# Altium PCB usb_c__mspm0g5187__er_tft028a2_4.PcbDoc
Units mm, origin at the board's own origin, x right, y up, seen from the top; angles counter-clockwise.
Board outline 64 x 33 mm, 2 copper layers (Top, Bottom), stack 0 mm thick; 33 components, 30 nets, 216 pads, 98 vias.
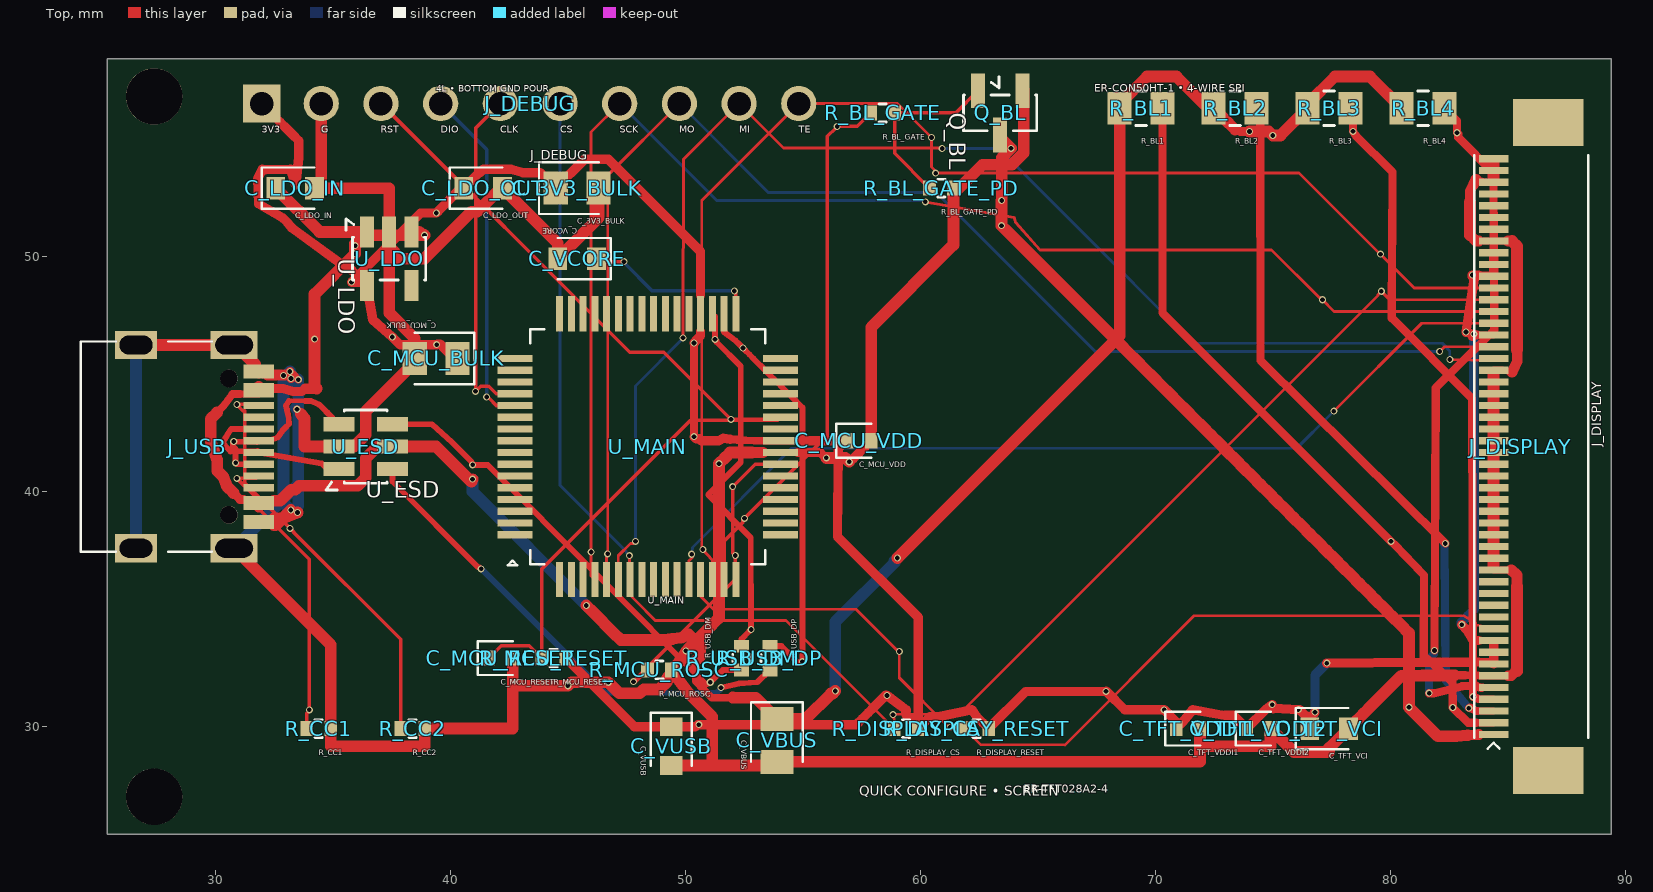
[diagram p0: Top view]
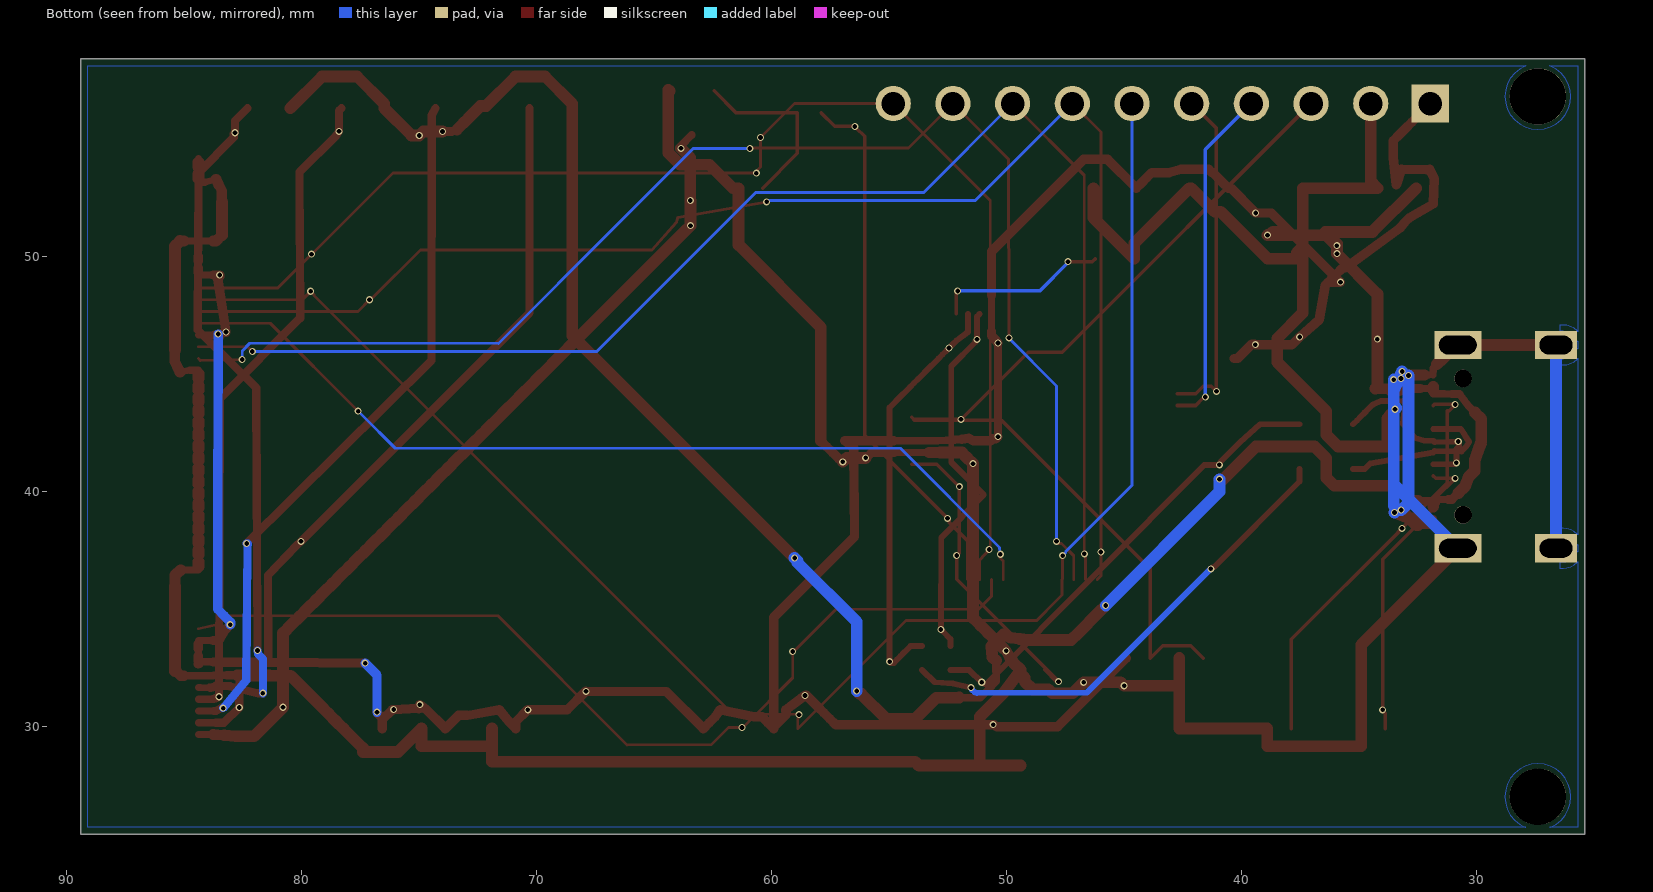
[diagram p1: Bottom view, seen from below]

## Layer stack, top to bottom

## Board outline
25.4,58.4 89.4,58.4 89.4,25.4 25.4,25.4

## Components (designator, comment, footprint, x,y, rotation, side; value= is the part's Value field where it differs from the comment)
C_3V3_BULK "" TSCIRCUIT-2.8500x1.4000mm 45.4,52.9 r0 top
C_LDO_IN "" TSCIRCUIT-2.4500x0.9500mm 33.4,52.9 r0 top
C_LDO_OUT "" TSCIRCUIT-2.4500x0.9500mm 41.4,52.9 r0 top
C_MCU_BULK "" TSCIRCUIT-2.8500x1.4000mm 39.4,45.65 r180 top
C_MCU_RESET "" TSCIRCUIT-1.5600x0.6400mm 42.15,32.9 r0 top
C_MCU_VDD "" TSCIRCUIT-1.5600x0.6400mm 57.4,42.15 r0 top
C_TFT_VCI "" TSCIRCUIT-2.4500x0.9500mm 77.4,29.9 r0 top
C_TFT_VDDI1 "" TSCIRCUIT-1.5600x0.6400mm 71.4,29.9 r0 top
C_TFT_VDDI2 "" TSCIRCUIT-1.5600x0.6400mm 74.4,29.9 r0 top
C_VBUS "" TSCIRCUIT-1.4000x2.8500mm 53.9,29.4 r270 top
C_VCORE "" TSCIRCUIT-2.4500x0.9500mm 45.4,49.9 r180 top
C_VUSB "" TSCIRCUIT-0.9500x2.4500mm 49.4,29.15 r270 top
J_DEBUG "" TSCIRCUIT-24.3600x1.5000mm 43.4,56.5 r0 top
J_DISPLAY "" TSCIRCUIT-4.4500x29.5800mm 86,41.9 r90 top
J_USB "" TSCIRCUIT-6.7732x9.8502mm 29.112,41.9 r90 top
Q_BL "" TSCIRCUIT-2.5000x3.3500mm 63.4,56.1 r270 top
R_BL1 "" TSCIRCUIT-2.8500x1.4000mm 69.4,56.3 r0 top
R_BL2 "" TSCIRCUIT-2.8500x1.4000mm 73.4,56.3 r0 top
R_BL3 "" TSCIRCUIT-2.8500x1.4000mm 77.4,56.3 r0 top
R_BL4 "" TSCIRCUIT-2.8500x1.4000mm 81.4,56.3 r0 top
R_BL_GATE "" TSCIRCUIT-1.5600x0.6400mm 58.4,56.1 r0 top
R_BL_GATE_PD "" TSCIRCUIT-1.5600x0.6400mm 60.9,52.9 r0 top
R_CC1 "" TSCIRCUIT-1.5600x0.6400mm 34.4,29.9 r0 top
R_CC2 "" TSCIRCUIT-1.5600x0.6400mm 38.4,29.9 r0 top
R_DISPLAY_CS "" TSCIRCUIT-1.5600x0.6400mm 59.4,29.9 r0 top
R_DISPLAY_RESET "" TSCIRCUIT-1.5600x0.6400mm 62.4,29.9 r0 top
R_MCU_RESET "" TSCIRCUIT-1.5600x0.6400mm 44.4,32.9 r0 top
R_MCU_ROSC "" TSCIRCUIT-1.5600x0.6400mm 48.9,32.4 r0 top
R_USB_DM "" TSCIRCUIT-0.6400x1.5600mm 52.4,32.9 r90 top
R_USB_DP "" TSCIRCUIT-0.6400x1.5600mm 53.6,32.9 r90 top
U_ESD "" TSCIRCUIT-3.6000x2.5000mm 36.4,41.9 r0 top
U_LDO "" TSCIRCUIT-2.5000x3.6000mm 37.4,49.9 r270 top
U_MAIN "" TSCIRCUIT-12.8000x12.8000mm 48.4,41.9 r0 top

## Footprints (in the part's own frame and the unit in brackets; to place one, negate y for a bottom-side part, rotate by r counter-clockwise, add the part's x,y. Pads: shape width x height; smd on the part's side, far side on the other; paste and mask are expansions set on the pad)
TSCIRCUIT-0.6400x1.5600mm [mm]
  rect 0.54x0.64 smd: 1(-0.51,0) 2(0.51,0)
  silkscreen extent -0.15,-0.38 0.15,0.38
TSCIRCUIT-0.9500x2.4500mm [mm]
  rect 0.8x0.95 smd: 1(-0.825,0) 2(0.825,0)
  silkscreen extent -1.43,-0.87 0.82,0.87
TSCIRCUIT-1.4000x2.8500mm [mm]
  rect 1.025x1.4 smd: 1(-0.913,0) 2(0.913,0)
  silkscreen extent -1.63,-1.1 0.91,1.1
TSCIRCUIT-1.5600x0.6400mm [mm]
  rect 0.54x0.64 smd: 1(-0.51,0) 2(0.51,0)
  silkscreen extent -0.98,-0.72 0.51,0.72
TSCIRCUIT-2.4500x0.9500mm [mm]
  rect 0.8x0.95 smd: 1(-0.825,0) 2(0.825,0)
  silkscreen extent -1.42,-0.88 0.82,0.87
TSCIRCUIT-2.5000x3.3500mm [mm]
  rect 1.475x0.6 smd: 1(-0.938,-0.95) 2(-0.938,0.95) 3(0.937,0)
  silkscreen extent -1.54,-1.56 0.76,1.56
TSCIRCUIT-2.5000x3.6000mm [mm]
  rect 1.325x0.6 smd: 1(-1.138,-0.95) 2(-1.138,0) 3(-1.138,0.95) 4(1.137,0.95) 5(1.137,-0.95)
  silkscreen extent -1.69,-1.84 0.91,1.56
TSCIRCUIT-2.8500x1.4000mm [mm]
  rect 1.025x1.4 smd: 1(-0.913,0) 2(0.913,0)
  silkscreen extent -1.63,-1.1 0.91,1.1
TSCIRCUIT-3.6000x2.5000mm [mm]
  rect 1.325x0.6 smd: 1(-1.138,-0.95) 2(-1.138,0) 3(-1.138,0.95) 4(1.137,0.95) 5(1.137,0) 6(1.137,-0.95)
  silkscreen extent -1.69,-1.84 0.91,1.56
TSCIRCUIT-4.4500x29.5800mm [mm]
  rect 0.3x1.25 smd: 1(-12.25,1.6) 2(-11.75,1.6) 3(-11.25,1.6) 4(-10.75,1.6) 5(-10.25,1.6) 6(-9.75,1.6) 7(-9.25,1.6) 8(-8.75,1.6) 9(-8.25,1.6) 10(-7.75,1.6) 11(-7.25,1.6) 12(-6.75,1.6) 13(-6.25,1.6) 14(-5.75,1.6) 15(-5.25,1.6) 16(-4.75,1.6) 17(-4.25,1.6) 18(-3.75,1.6) 19(-3.25,1.6) 20(-2.75,1.6) 21(-2.25,1.6) 22(-1.75,1.6) 23(-1.25,1.6) 24(-0.75,1.6) 25(-0.25,1.6) 26(0.25,1.6) 27(0.75,1.6) 28(1.25,1.6) 29(1.75,1.6) 30(2.25,1.6) 31(2.75,1.6) 32(3.25,1.6) 33(3.75,1.6) 34(4.25,1.6) 35(4.75,1.6) 36(5.25,1.6) 37(5.75,1.6) 38(6.25,1.6) 39(6.75,1.6) 40(7.25,1.6) 41(7.75,1.6) 42(8.25,1.6) 43(8.75,1.6) 44(9.25,1.6) 45(9.75,1.6) 46(10.25,1.6) 47(10.75,1.6) 48(11.25,1.6) 49(11.75,1.6) 50(12.25,1.6)
  rect 2x3 smd: 51(13.79,-0.725) 52(-13.79,-0.725)
  silkscreen extent -12.85,-2.42 12.4,2.43
TSCIRCUIT-6.7732x9.8502mm [mm]
  rect 0.3x1.3 smd: 1(-3.35,-2.737) 2(-3.05,-2.737) 3(-2.55,-2.737) 4(-2.25,-2.737) 5(-1.75,-2.737) 6(-1.25,-2.737) 7(-0.75,-2.737) 8(-0.25,-2.737) 9(0.25,-2.737) 10(0.75,-2.737) 11(1.25,-2.737) 12(1.75,-2.737) 13(2.55,-2.737) 14(2.25,-2.737) 15(3.35,-2.737) 16(3.05,-2.737)
  rect 1.2x2 hole 0.8 slot 1.6 at 90 deg: 17(-4.325,-1.693) 18(4.325,-1.693)
  rect 1.2x1.8 hole 0.8 slot 1.4 at 90 deg: 19(4.325,2.487) 20(-4.325,2.487)
  round 0.75 hole 0.75 unplated: NPTH-1(-2.9,-1.468) NPTH-2(2.9,-1.468)
  silkscreen extent -4.47,-0.75 4.47,4.83
TSCIRCUIT-12.8000x12.8000mm [mm]
  rect 1.5x0.3 smd: 1(-5.65,-3.75) 2(-5.65,-3.25) 3(-5.65,-2.75) 4(-5.65,-2.25) 5(-5.65,-1.75) 6(-5.65,-1.25) 7(-5.65,-0.75) 8(-5.65,-0.25) 9(-5.65,0.25) 10(-5.65,0.75) 11(-5.65,1.25) 12(-5.65,1.75) 13(-5.65,2.25) 14(-5.65,2.75) 15(-5.65,3.25) 16(-5.65,3.75) 33(5.65,3.75) 34(5.65,3.25) 35(5.65,2.75) 36(5.65,2.25) 37(5.65,1.75) 38(5.65,1.25) 39(5.65,0.75) 40(5.65,0.25) 41(5.65,-0.25) 42(5.65,-0.75) 43(5.65,-1.25) 44(5.65,-1.75) 45(5.65,-2.25) 46(5.65,-2.75) 47(5.65,-3.25) 48(5.65,-3.75)
  rect 0.3x1.5 smd: 17(-3.75,5.65) 18(-3.25,5.65) 19(-2.75,5.65) 20(-2.25,5.65) 21(-1.75,5.65) 22(-1.25,5.65) 23(-0.75,5.65) 24(-0.25,5.65) 25(0.25,5.65) 26(0.75,5.65) 27(1.25,5.65) 28(1.75,5.65) 29(2.25,5.65) 30(2.75,5.65) 31(3.25,5.65) 32(3.75,5.65) 49(3.75,-5.65) 50(3.25,-5.65) 51(2.75,-5.65) 52(2.25,-5.65) 53(1.75,-5.65) 54(1.25,-5.65) 55(0.75,-5.65) 56(0.25,-5.65) 57(-0.25,-5.65) 58(-0.75,-5.65) 59(-1.25,-5.65) 60(-1.75,-5.65) 61(-2.25,-5.65) 62(-2.75,-5.65) 63(-3.25,-5.65) 64(-3.75,-5.65)
  silkscreen extent -5.95,-5.05 5,5
TSCIRCUIT-24.3600x1.5000mm [mm]
  rect 1.6x1.6 hole 1: 1(-11.43,0)
  round 1.5 hole 1: 2(-8.89,0) 3(-6.35,0) 4(-3.81,0) 5(-1.27,0) 6(1.27,0) 7(3.81,0) 8(6.35,0) 9(8.89,0) 10(11.43,0)

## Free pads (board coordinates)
  round 2.4 hole 2.4 unplated: NPTH-3(27.4,27) NPTH-4(27.4,56.8)

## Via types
v1: diameter 0.3, hole 0.2, Top to Bottom, 98 vias

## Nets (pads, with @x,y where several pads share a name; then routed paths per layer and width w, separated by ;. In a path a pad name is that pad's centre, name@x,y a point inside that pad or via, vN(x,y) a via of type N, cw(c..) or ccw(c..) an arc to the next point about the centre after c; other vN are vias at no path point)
".J_DEBUG > .pin4 to .U_MAIN > .pin12": J_DEBUG.4 U_MAIN.12 | length 14.7
  Top w0.15: v1(41.548,44.013) 41.588,43.973 41.634,43.973 41.958,43.65 U_MAIN.12
  Bottom w0.15: J_DEBUG.4 41.548,54.542 v1(41.548,44.013)
".J_DEBUG > .pin5 to .U_MAIN > .pin13": J_DEBUG.5 U_MAIN.13 | length 14.6
  Top w0.15: J_DEBUG.5 41.075,55.445 v1(41.075,44.251) 41.294,44.47 41.633,44.47 41.953,44.15 U_MAIN.13
".U_MAIN > .pin42 to .R_MCU_ROSC > .pin1": R_MCU_ROSC.1 U_MAIN.42 | length 13.4
  Top w0.15: R_MCU_ROSC.1 47.89,31.9 v1(47.8,31.9) 47.923,32.023 47.923,32.046 52.129,36.252 v1(52.129,37.265) 52.017,37.361 52.017,37.445 v1(52.017,40.195) 52.144,40.322 52.972,41.15 U_MAIN.42
BACKLIGHT_ANODE_1: J_DISPLAY.2 R_BL1.2 | length 32.6
  Top w0.3: 83.744,30.15 83.775,30.15 83.838,30.15 83.931,30.15 84.025,30.15 84.119,30.15 84.213,30.15 84.306,30.15 J_DISPLAY.2
  Top w0.312: 83.65,30.15 83.744,30.15
  Top w0.35: R_BL1.2 70.313,47.594 v1(80.036,37.871) 80.151,37.756 ; 80.152,37.756 81.436,36.429 81.422,33.01 82.654,31.872 v1(82.66,30.798) 82.675,30.783 83.308,30.15 83.65,30.15
BACKLIGHT_ANODE_2: J_DISPLAY.3 R_BL2.2 | length 30.4
  Top w0.3: 83.744,30.65 83.775,30.65 83.838,30.65 83.931,30.65 84.025,30.65 84.119,30.65 84.213,30.65 84.306,30.65 J_DISPLAY.3
  Top w0.35: R_BL2.2 74.472,56.001 74.482,45.566 v1(82.347,37.776) ; v1(83.347,30.772) 83.398,30.8 83.437,30.77 83.651,30.651 83.652,30.65 83.744,30.65
  Bottom w0.35: v1(82.347,37.776) 82.292,37.763 82.313,37.662 82.364,31.949 v1(83.347,30.772)
BACKLIGHT_ANODE_3: J_DISPLAY.4 R_BL3.2 | length 28.1
  Top w0.3: J_DISPLAY.4@83.782,31.157 83.838,31.15 83.931,31.15 84.025,31.15 84.119,31.15 84.213,31.15 84.306,31.15 J_DISPLAY.4
  Top w0.35: R_BL3.2 78.419,56.194 v1(78.419,55.318) 78.529,55.154 78.529,55.145 80.092,53.582 80.068,47.366 83.482,43.951 v1(83.523,31.256) 83.648,31.203 83.671,31.193 83.709,31.177 83.753,31.162 J_DISPLAY.4@83.782,31.157
BACKLIGHT_ANODE_4: J_DISPLAY.5 R_BL4.2 | length 29.8
  Top w0.3: J_DISPLAY.5@83.784,31.661 83.838,31.65 J_DISPLAY.5@83.931,31.65 ; J_DISPLAY.5@83.883,31.633 84.306,31.65 J_DISPLAY.5
  Top w0.337: J_DISPLAY.5@83.883,31.633 J_DISPLAY.5@83.931,31.65
  Top w0.35: v1(81.656,31.407) 81.751,31.406 81.85,31.4 83.05,31.7 83.66,31.726 83.759,31.672 J_DISPLAY.5@83.784,31.661 ; v1(81.888,33.224) 81.934,44.389 84.428,46.864 84.4,53.548 82.898,55.05 82.898,55.204 v1(82.845,55.257) 82.845,55.768 R_BL4.2
  Bottom w0.35: v1(81.656,31.407) 81.656,32.866 81.857,33.071 81.858,33.108 v1(81.888,33.224)
BACKLIGHT_CATHODE: J_DISPLAY.1 Q_BL.3 | length 36
  Top w0.3: J_DISPLAY.1@83.775,29.65 83.838,29.65 83.931,29.65 84.025,29.65 84.119,29.65 84.213,29.65 84.306,29.65 J_DISPLAY.1
  Top w0.325: Q_BL.3 63.863,54.7 v1(63.863,54.594)
  Top w0.45: 83.296,29.614 J_DISPLAY.1@83.775,29.65
  Top w0.5: v1(63.863,54.594) 63.465,54.197 v1(63.465,52.372) 63.458,52.365 63.458,52.302 63.458,51.802 v1(63.458,51.303) 63.586,51.175 63.938,50.824 64.289,50.472 64.64,50.121 64.992,49.77 65.343,49.419 65.694,49.067 66.045,48.716 66.397,48.365 66.748,48.014 67.099,47.662 67.45,47.311 67.802,46.96 68.153,46.609 68.504,46.257 68.855,45.906 69.207,45.555 69.558,45.204 69.909,44.852 70.26,44.501 70.612,44.15 70.963,43.799 71.314,43.447 71.665,43.096 72.017,42.745 72.368,42.394 72.719,42.042 73.07,41.691 73.422,41.34 73.773,40.989 74.124,40.637 74.475,40.286 74.827,39.935 75.178,39.584 75.529,39.232 75.88,38.881 76.232,38.53 76.583,38.179 76.934,37.827 77.285,37.476 77.637,37.125 77.988,36.774 78.339,36.422 78.69,36.071 79.042,35.72 79.393,35.369 79.744,35.017 80.095,34.666 80.447,34.315 80.798,33.964 80.798,33.513 80.798,33.062 80.798,32.611 80.798,32.16 80.798,31.71 80.798,31.259 v1(80.798,30.808) 82.029,29.577 82.817,29.577 83.296,29.614
BACKLIGHT_GATE: Q_BL.1 R_BL_GATE.2 R_BL_GATE_PD.1 | length 7.7
  Top w0.15: R_BL_GATE_PD.1 58.91,54.38 R_BL_GATE.2 61.513,56.1 Q_BL.1
BACKLIGHT_PWM: R_BL_GATE.1 U_MAIN.50 | length 22.9
  Top w0.15: U_MAIN.50 51.65,37.877 52.444,38.671 52.444,38.771 v1(52.52,38.847) 56.044,42.371 56.044,55.101 56.397,55.455 56.397,55.457 v1(56.467,55.527) 57.317,55.527 R_BL_GATE.1
DISPLAY_CS_N: J_DEBUG.6 J_DISPLAY.38 R_DISPLAY_CS.1 U_MAIN.58 | length 69.6
  Top w0.12: v1(47.622,37.261) 47.622,36.278 U_MAIN.58 47.65,35.579 47.883,35.346 48.723,34.506 54.284,34.506 R_DISPLAY_CS.1 58.89,30.338 58.846,30.382 v1(58.84,30.496) 61.674,30.52 79.485,48.331 79.485,48.376 v1(79.62,48.511) 79.981,48.15 J_DISPLAY.38
  Bottom w0.12: J_DEBUG.6 44.67,40.254 47.491,37.432 47.491,37.392 v1(47.622,37.261)
DISPLAY_DC: J_DISPLAY.36 U_MAIN.53 | length 39.5
  Top w0.12: U_MAIN.53 50.15,37.037 50.301,37.187 50.301,37.332 v1(50.273,37.32) ; v1(77.602,43.41) 81.342,47.15 J_DISPLAY.36
  Bottom w0.12: v1(50.273,37.32) 50.302,37.605 54.528,41.831 76.025,41.831 77.439,43.245 77.439,43.247 v1(77.602,43.41)
DISPLAY_MISO: J_DEBUG.9 J_DISPLAY.33 U_MAIN.59 | length 59.3
  Top w0.12: U_MAIN.59 47.15,37.256 47.672,37.778 47.791,37.778 v1(47.88,37.867) ; v1(49.905,46.53) 49.919,54.129 J_DEBUG.9 54.183,54.607 60.717,54.607 60.911,54.607 v1(60.933,54.585) ; v1(82.535,45.606) 84.321,45.571 J_DISPLAY.33
  Bottom w0.12: v1(47.88,37.867) 47.88,44.484 49.917,46.521 v1(49.905,46.53) ; v1(60.933,54.585) 63.34,54.585 66.586,51.339 71.632,46.293 82.216,46.301 82.535,45.976 82.53,45.681 82.53,45.611 v1(82.535,45.606)
DISPLAY_MOSI: J_DEBUG.8 J_DISPLAY.34 U_MAIN.60 | length 60.6
  Top w0.12: U_MAIN.60 46.65,37.188 46.694,37.232 46.694,37.33 v1(46.7,37.336) 46.7,53.45 J_DEBUG.8 ; v1(82.105,45.951) 82.304,46.15 J_DISPLAY.34
  Bottom w0.12: J_DEBUG.8 53.534,52.716 60.682,52.716 67.449,45.949 81.879,45.949 82.037,45.949 v1(82.105,45.951)
DISPLAY_RESET_N: J_DISPLAY.10 R_DISPLAY_RESET.1 U_MAIN.52 | length 40.2
  Top w0.12: U_MAIN.52 50.65,35.531 51.202,34.979 57.267,34.979 58.988,33.258 59.029,33.258 v1(59.108,33.179) 59.108,32.067 61.184,29.991 61.22,29.991 v1(61.264,29.947) 61.843,29.947 R_DISPLAY_RESET.1 62.581,29.209 66.16,29.205 71.652,34.7 83.129,34.703 83.304,34.601 83.584,34.33 J_DISPLAY.10
DISPLAY_SCLK: J_DEBUG.7 J_DISPLAY.37 U_MAIN.61 | length 61.6
  Top w0.12: U_MAIN.61 45.994,36.406 v1(45.994,37.419) 45.994,37.504 45.994,55.284 J_DEBUG.7 ; v1(60.217,52.315) 63.986,51.656 64.06,51.44 65.1,50.272 74.951,50.272 77,48.222 77.043,48.222 v1(77.114,48.151) 77.615,47.65 J_DISPLAY.37
  Bottom w0.12: J_DEBUG.7 51.34,52.37 59.999,52.37 60.208,52.37 v1(60.217,52.315)
DISPLAY_TE: J_DEBUG.10 J_DISPLAY.39 U_MAIN.51 | length 55.8
  Top w0.12: U_MAIN.51 51.15,37.077 v1(50.746,37.523) 50.688,37.539 50.7,37.55 50.7,39.711 50.7,52.37 J_DEBUG.10 59.035,56.5 60.481,55.054 v1(60.483,55.052) 60.483,53.793 60.652,53.624 60.652,53.544 v1(60.657,53.539) 76.119,53.539 79.503,50.155 79.519,50.155 v1(79.585,50.089) 81.024,48.65 J_DISPLAY.39
GND: C_3V3_BULK.2 C_LDO_IN.2 C_LDO_OUT.2 C_MCU_BULK.2 C_MCU_RESET.2 C_MCU_VDD.2 C_TFT_VCI.2 C_TFT_VDDI1.2 C_TFT_VDDI2.2 C_VBUS.2 C_VCORE.2 C_VUSB.2 J_DEBUG.2 J_DISPLAY.6 J_DISPLAY.15 J_DISPLAY.16 J_DISPLAY.17 J_DISPLAY.18 J_DISPLAY.19 J_DISPLAY.20 J_DISPLAY.21 J_DISPLAY.22 J_DISPLAY.23 J_DISPLAY.24 J_DISPLAY.25 J_DISPLAY.26 J_DISPLAY.27 J_DISPLAY.28 J_DISPLAY.29 J_DISPLAY.30 J_DISPLAY.31 J_DISPLAY.32 J_DISPLAY.43 J_DISPLAY.48 J_DISPLAY.49 J_DISPLAY.50 J_USB.1 J_USB.2 J_USB.15 J_USB.16 J_USB.17 J_USB.18 J_USB.19 J_USB.20 Q_BL.2 R_BL_GATE_PD.2 R_CC1.2 R_CC2.2 R_MCU_ROSC.2 U_ESD.2 U_LDO.2 U_MAIN.41 | length 223.4
  Top w0.275: J_USB.16@32.335,44.95 J_USB.16 32.875,44.95 v1(32.9,44.925)
  Top w0.288: J_USB.16@31.849,45.1 J_USB.16 ; J_USB.16@32.037,44.95 J_USB.16@31.945,44.961 ; J_USB.16 J_USB.16@31.945,44.961 ; J_USB.16 J_USB.16@31.945,44.961
  Top w0.3: 31.699,45.4 J_USB.15 J_USB.16@31.849,45.1 ; J_USB.1 32.208,38.55 J_USB.1@32.499,38.55 ; J_USB.2 31.945,38.839 32.036,38.85 32.13,38.85 32.224,38.85 32.318,38.85 32.411,38.85 J_USB.2@32.499,38.85 ; J_USB.16@31.945,44.961 J_USB.16@32.037,44.95 ; 32.718,44.972 J_USB.16@32.224,44.95 ; 53.3,41.65 53.394,41.65 53.488,41.65 53.581,41.65 53.675,41.65 53.769,41.65 53.863,41.65 53.956,41.65 U_MAIN.41 54.144,41.65 54.237,41.65 54.331,41.65 54.425,41.65 54.519,41.65 54.612,41.65 54.706,41.65 U_MAIN.41@54.8,41.65 ; 83.65,53.275 84.112,53.15 J_DISPLAY.48 84.4,53.3 ; J_DISPLAY.43@83.775,50.65 84.088,50.65 J_DISPLAY.43 84.713,50.65 85.025,50.65 ; J_DISPLAY.6@83.838,32.15 83.931,32.15 84.025,32.15 84.119,32.15 84.213,32.15 84.306,32.15 J_DISPLAY.6 84.775,32.15 85.025,32.15 ; 84.4,36.8 J_DISPLAY.15 84.775,36.65 85.15,36.65 ; J_DISPLAY.16@84.4,37 J_DISPLAY.16 J_DISPLAY.16@84.4,37.3 ; J_DISPLAY.17@84.4,37.5 J_DISPLAY.17 J_DISPLAY.17@84.4,37.8 ; J_DISPLAY.18@84.4,38 J_DISPLAY.18 84.4,38.3 ; J_DISPLAY.19@84.4,38.5 J_DISPLAY.19 84.4,38.8 ; J_DISPLAY.20@84.4,39 J_DISPLAY.20 J_DISPLAY.20@84.4,39.3 ; J_DISPLAY.21@84.4,39.5 J_DISPLAY.21 84.4,39.8 ; J_DISPLAY.22@84.4,40 J_DISPLAY.22 J_DISPLAY.22@84.4,40.3 ; J_DISPLAY.23@84.4,40.5 J_DISPLAY.23 J_DISPLAY.23@84.4,40.8 ; J_DISPLAY.24@84.4,41 J_DISPLAY.24 84.4,41.3 ; J_DISPLAY.25@84.4,41.5 J_DISPLAY.25 84.4,41.8 ; J_DISPLAY.26@84.4,42 J_DISPLAY.26 84.4,42.3 ; J_DISPLAY.27@84.4,42.5 J_DISPLAY.27 J_DISPLAY.27@84.4,42.8 ; J_DISPLAY.28@84.4,43 J_DISPLAY.28 84.4,43.3 ; J_DISPLAY.29@84.4,43.5 J_DISPLAY.29 84.4,43.8 ; J_DISPLAY.30@84.4,44 J_DISPLAY.30 J_DISPLAY.30@84.4,44.3 ; J_DISPLAY.31@84.4,44.5 J_DISPLAY.31 84.4,44.8 ; J_DISPLAY.32@84.4,45 J_DISPLAY.32 84.775,45.15 85.181,45.072 ; J_DISPLAY.49@84.4,53.5 J_DISPLAY.49 84.4,53.8 ; J_DISPLAY.50@84.4,54 J_DISPLAY.50 ; J_USB.16@32.037,44.95 J_USB.16@32.13,44.95 ; J_USB.16@32.037,44.95 J_USB.16@32.13,44.95 ; J_USB.16@32.13,44.95 J_USB.16@32.224,44.95 ; J_USB.16@32.13,44.95 J_USB.16@32.224,44.95
  Top w0.325: 33.318,44.95 33.338,44.95 v1(33.536,44.752) ; v1(33.478,43.49) 33.638,43.294 ; v1(50.025,33.208) 50.158,33.312 50.158,33.334 ; v1(56.978,41.251) 57.151,41.391 ; 83.196,32.171 83.65,32.175 83.746,32.165 83.777,32.156 J_DISPLAY.6@83.838,32.15
  Top w0.375: J_USB.16@32.335,44.95 32.82,44.95 33.305,44.95 v1(33.225,44.8) ; v1@32.959,44.95 33.318,44.95 ; v1(33.175,45.1) v1@33.212,44.994 ; U_MAIN.41@54.8,41.65 55.275,41.65 55.75,41.65 v1@55.962,41.438 ; 82.743,32.168 83.196,32.171
  Top w0.4: v1@55.962,41.438 55.988,41.438 v1(56.006,41.42) ; 57.151,41.391 57.404,41.644 57.657,41.897 C_MCU_VDD.2
  Top w0.425: 32.718,44.972 v1@33.212,44.994
  Top w0.437: 83.4,52.306 83.4,52.775 83.525,53.025
  Top w0.45: 49.871,32.958 v1(50.025,33.208) ; 83.431,50.869 83.65,50.65 J_DISPLAY.43@83.775,50.65 ; 83.525,53.025 83.65,53.275 ; 85.025,32.15 85.15,32.15 85.338,32.337 ; 85.181,45.072 85.291,45.298 85.4,45.525 85.4,46.012
  Top w0.475: J_USB.16@32.224,44.95 32.591,44.95 v1@32.959,44.95 ; 52.836,41.65 53.3,41.65 ; 85.025,50.65 85.181,50.65 ; 85.15,36.65 85.4,36.431 85.4,35.969
  Top w0.5: J_USB.19 J_USB.18 ; J_USB.17 34.91,33.471 R_CC1.2 34.91,29.15 38.91,29.15 R_CC2.2 42.66,29.9 C_MCU_RESET.2 42.66,31.723 v1(45.001,31.723) 45.023,31.745 45.03,31.745 45.154,31.868 45.547,31.868 45.941,31.868 46.334,31.868 v1(46.728,31.868) 47.196,31.4 48.067,31.4 48.233,31.567 48.9,31.567 49.233,31.9 49.233,32.067 49.41,32.243 R_MCU_ROSC.2 ; J_USB.18 30.874,46.225 31.474,45.625 31.699,45.4 ; 32.499,38.55 32.567,38.55 32.891,38.875 v1(33.216,39.2) ; 32.499,38.85 32.505,38.85 32.599,38.85 32.867,38.85 v1(33.5,39.1) ; 33.638,43.294 33.797,43.098 33.797,41.9 U_ESD.2 35.9,41.9 36.4,42.4 36.4,43.4 38.487,45.488 C_MCU_BULK.2 38.487,46.076 38.487,46.501 37.4,47.589 U_LDO.2 ; J_DEBUG.2 34.51,53.185 C_LDO_IN.2 37.4,52.9 U_LDO.2 ; C_3V3_BULK.2 46.313,51.637 C_VCORE.2 44.575,50.55 C_LDO_OUT.2 42.15,52.9 41.15,51.9 40.9,51.9 38.9,49.9 37.65,49.9 37.65,50.15 37.4,50.4 U_LDO.2 ; 49.716,32.706 R_MCU_ROSC.2 ; 49.716,32.708 49.871,32.958 ; 50.158,33.334 50.478,33.654 50.797,33.973 51.117,34.292 51.436,34.612 51.436,35.081 51.436,35.55 51.436,36.019 51.436,36.488 51.436,36.957 51.436,37.425 51.436,37.894 51.436,38.363 51.436,38.832 51.436,39.301 51.436,39.77 51.436,40.239 51.436,40.708 v1(51.436,41.177) 51.479,41.22 51.694,41.435 51.909,41.65 52.373,41.65 52.836,41.65 ; v1(56.006,41.42) 56.809,41.42 v1(56.978,41.251) ; C_MCU_VDD.2 57.91,42.633 57.91,43.117 57.91,43.6 57.91,44.083 57.91,44.567 57.91,45.05 57.91,45.533 57.91,46.017 57.91,46.5 57.91,46.983 61.41,50.483 R_BL_GATE_PD.2 61.65,52.9 62.65,53.9 63.9,53.9 64.4,54.4 64.4,57.088 Q_BL.2 ; 82.743,32.168 82.289,32.164 81.836,32.161 81.382,32.157 80.929,32.154 80.475,32.15 80.154,31.829 79.832,31.507 79.511,31.186 79.189,30.864 78.868,30.543 78.546,30.221 C_TFT_VCI.2 77.4,29.075 77.4,28.9 75.91,28.9 C_TFT_VDDI2.2 74.91,29.15 71.91,29.15 C_TFT_VDDI1.2 71.91,28.487 66.104,28.487 65.616,28.487 65.128,28.487 64.64,28.487 64.151,28.487 63.663,28.487 63.175,28.487 62.687,28.487 62.199,28.487 61.711,28.487 61.222,28.487 60.734,28.487 60.246,28.487 59.758,28.487 59.27,28.487 58.782,28.487 58.293,28.487 57.805,28.487 57.317,28.487 56.829,28.487 56.341,28.487 55.853,28.487 55.364,28.487 54.876,28.487 54.388,28.487 C_VBUS.2 53.737,28.325 C_VUSB.2 51.15,28.325 51.15,30.4 50.15,31.4 R_MCU_ROSC.2 ; 83.4,52.306 83.4,50.9 83.431,50.869 ; 84.4,36.8 J_DISPLAY.16@84.4,37 ; 84.4,37.3 84.4,37.5 ; 84.4,37.8 J_DISPLAY.18@84.4,38 ; 84.4,38.3 J_DISPLAY.19@84.4,38.5 ; 84.4,38.8 84.4,39 ; J_DISPLAY.20@84.4,39.3 J_DISPLAY.21@84.4,39.5 ; 84.4,39.8 84.4,40 ; 84.4,40.3 84.4,40.5 ; 84.4,40.8 J_DISPLAY.24@84.4,41 ; 84.4,41.3 84.4,41.5 ; 84.4,41.8 J_DISPLAY.26@84.4,42 ; 84.4,42.3 84.4,42.5 ; J_DISPLAY.27@84.4,42.8 84.4,43 ; 84.4,43.3 J_DISPLAY.29@84.4,43.5 ; 84.4,43.8 84.4,44 ; J_DISPLAY.30@84.4,44.3 J_DISPLAY.31@84.4,44.5 ; 84.4,44.8 84.4,45 ; 84.4,53.3 J_DISPLAY.49@84.4,53.5 ; 84.4,53.8 84.4,54 ; 85.181,50.65 85.4,50.431 85.4,50.172 85.4,49.913 85.4,49.425 85.4,48.937 85.4,48.45 85.4,47.962 85.4,47.475 85.4,46.988 85.4,46.5 85.4,46.012 ; 85.338,32.337 85.4,32.337 85.4,35.969
  Bottom w0.5: J_USB.20 J_USB.19 ; J_USB.17 33.536,40.305 v1(33.536,44.752) ; v1(32.9,44.925) 32.9,39.516 v1(33.216,39.2) ; v1(33.175,45.1) 33.536,44.264 33.536,43.775 33.536,43.287 33.536,42.798 33.536,42.31 33.536,41.821 33.536,41.333 33.536,40.845 33.536,40.356 33.536,39.868 33.536,39.379 33.384,39.227 33.244,39.227 v1(33.5,39.1) ; v1(33.225,44.8) 33.536,44.39 33.536,44.028 33.536,43.666 33.421,43.551 33.421,43.53 v1(33.478,43.49)
MAIN_RESET: C_MCU_RESET.1 J_DEBUG.3 R_MCU_RESET.1 U_MAIN.38 | length 41.9
  Top w0.15: J_DEBUG.3 47.634,45.916 49.088,45.916 ; C_MCU_RESET.1 42.17,33.43 43.36,33.43 R_MCU_RESET.1 43.89,36.692 50.224,43.026 53.926,43.026 U_MAIN.38 53.962,43.062 v1(51.943,43.062) 51.916,43.089 49.089,45.916
MSP_VCORE: C_VCORE.1 U_MAIN.32 | length 7.5
  Top w0.15: C_VCORE.1 46.354,49.771 v1(47.391,49.771) ; v1(52.091,48.525) 52.15,48.466 U_MAIN.32
  Bottom w0.15: v1(47.391,49.771) 47.377,49.757 47.377,49.751 48.603,48.525 v1(52.091,48.525)
usb-dm-mcu: R_USB_DM.2 U_MAIN.30 | length 16.1
  Top w0.25: U_MAIN.30 51.269,47.431 v1(51.269,46.463) 51.328,46.404 51.328,46.353 52.361,45.32 52.361,45.282 52.361,41.236 50.977,39.852 52.788,38.022 v1(52.804,34.121) 52.714,34.03 52.4,33.717 R_USB_DM.2
usb-dm-phy: R_USB_DM.1 U_ESD.4 | length 19.7
  Top w0.25: U_ESD.4 39.22,42.85 40.074,42.085 40.9,41.25 v1(40.951,41.123) 41.593,41.12 50.885,31.785 50.992,31.81 v1(51.063,31.872) 51.594,32.39 R_USB_DM.1
usb-dm-port: J_USB.7 J_USB.9 U_ESD.3 | length 8.2
  Top w0.188: 33.131,43.84 33.159,43.849 33.382,43.847 33.605,43.846 33.827,43.845
  Top w0.238: 33.009,43.65 33.131,43.84
  Top w0.25: J_USB.7 30.928,41.15 30.873,41.205 v1(30.866,41.212) 30.866,41.786 30.742,41.91 30.742,42.07 v1(30.786,42.114) 31.787,42.088 J_USB.9 32.041,42.15 32.234,42.15 32.65,42.275 32.853,42.577 32.995,42.719 33.138,42.861 33.127,43.11 33.088,43.29 33.049,43.47 33.009,43.65 ; 33.827,43.845 34.05,43.844 34.438,43.678 34.603,43.512 34.768,43.347 34.933,43.181 35.098,43.016 U_ESD.3
usb-dp-mcu: R_USB_DP.2 U_MAIN.31 | length 17.9
  Top w0.25: U_MAIN.31 51.65,47.333 51.65,47.115 51.65,46.898 51.65,46.775 52.133,46.415 52.294,46.254 v1(52.455,46.093) 52.557,45.992 52.73,45.818 52.903,45.645 53.077,45.472 53.25,45.298 53.423,45.125 53.597,44.952 53.77,44.778 53.943,44.605 54.116,44.432 54.29,44.258 54.463,44.085 54.636,43.912 54.81,43.738 54.983,43.565 54.983,43.319 54.983,43.073 54.983,42.828 54.983,42.582 54.983,42.336 54.983,42.09 54.983,41.844 54.983,41.598 54.983,41.352 54.983,41.107 54.983,40.861 54.983,40.615 54.983,40.369 54.983,40.123 54.983,39.877 54.983,39.631 54.983,39.386 54.983,39.14 54.983,38.894 54.983,38.648 54.983,38.402 54.983,38.156 54.983,37.911 54.983,37.665 54.983,37.419 54.983,37.173 54.983,36.927 54.983,36.681 54.983,36.435 54.983,36.19 54.983,35.944 54.983,35.698 54.983,35.452 54.983,35.206 54.983,34.96 54.983,34.714 54.983,34.469 54.983,34.223 54.983,33.977 54.983,33.731 54.983,33.485 54.983,33.239 54.983,32.994 v1(54.983,32.748) 54.934,32.699 54.805,32.699 54.663,32.841 54.521,32.983 54.379,33.126 54.236,33.268 54.094,33.41 53.847,33.41 R_USB_DP.2
usb-dp-phy: R_USB_DP.1 U_ESD.6 | length 20.7
  Top w0.25: U_ESD.6 37.537,40.413 41.181,36.769 41.246,36.769 v1(41.317,36.698) ; v1(51.524,31.643) 52.294,31.816 53.064,31.873 R_USB_DP.1
  Bottom w0.25: v1(41.317,36.698) 46.591,31.424 51.258,31.417 51.335,31.424 51.456,31.545 51.476,31.545 v1(51.524,31.643)
usb-dp-port: J_USB.8 J_USB.10 U_ESD.1 | length 7.1
  Top w0.25: J_USB.10 30.678,42.65 30.318,42.09 30.457,41.894 30.653,41.691 31.792,41.707 J_USB.8 34.53,41.183 34.763,40.95 U_ESD.1
USB_CC1: J_USB.6 R_CC1.1 | length 12.9
  Top w0.15: J_USB.6 31.748,40.549 v1(30.917,40.549) 31.007,40.463 31.007,40.458 31.64,39.825 31.64,39.471 34,37.111 v1(34,30.7) 33.966,30.666 33.966,30.619 33.89,30.543 R_CC1.1
USB_CC2: J_USB.12 R_CC2.1 | length 17.7
  Top w0.15: J_USB.12 31.806,43.693 v1(30.916,43.693) 30.948,43.661 31.176,43.433 31.254,43.433 31.257,40.352 v1(33.182,38.424) 33.331,38.275 33.331,38.261 37.89,33.702 R_CC2.1
VBUS5: C_LDO_IN.1 C_VBUS.1 J_USB.3 J_USB.4 J_USB.13 J_USB.14 R_BL1.1 R_BL2.1 R_BL3.1 R_BL4.1 U_ESD.5 U_LDO.1 U_LDO.3 | length 105.4
  Top w0.3: 31.048,44.145 31.363,44.15 J_USB.14 J_USB.14@31.849,44.3 ; J_USB.4@31.199,39.65 J_USB.4 ; J_USB.3@31.849,39.5 J_USB.4 ; J_USB.4@32.499,39.6 32.2,39.6 31.9,39.6 J_USB.4
  Top w0.303: J_USB.13 31.916,44.375 J_USB.13@32.397,44.374
  Top w0.325: 30.074,43.347 30.341,43.615 30.537,43.877 30.733,44.14 ; 50.449,32.353 50.449,31.913 50.771,31.569 51.12,31.22 52.025,31.22
  Top w0.35: 30.733,44.14 31.048,44.145
  Top w0.375: 30.775,39.931 31.056,39.65 31.199,39.65 ; 50.449,32.353 50.45,32.793 ; 73.401,55.386 73.619,55.306 v1(74.009,55.308)
  Top w0.387: 32.878,44.373 33.306,44.244 33.681,44.244 33.84,44.371
  Top w0.4: J_USB.13@32.397,44.374 32.878,44.373
  Top w0.45: 33.84,44.371 34.321,44.369
  Top w0.475: 73.097,55.691 73.401,55.386
  Top w0.5: 30.074,43.347 29.806,43.08 29.806,42.586 29.806,42.093 29.944,41.717 30.081,41.341 30.081,40.864 30.356,40.589 30.494,40.213 30.775,39.931 ; J_USB.3 J_USB.3@31.849,39.5 ; J_USB.13@31.849,44.3 J_USB.13 ; 32.499,39.6 32.767,39.6 33.233,40.067 33.4,40.067 33.567,40.233 36.067,40.233 36.4,40.567 36.4,41.233 36.4,41.4 36.9,41.9 U_ESD.5 39.4,41.9 40.9,40.4 40.9,40.467 v1(40.948,40.515) ; C_LDO_IN.1 34.438,51.038 U_LDO.1 ; 34.321,44.369 34.227,44.464 v1(34.227,46.471) 34.227,48.392 v1(35.946,50.112) 35.946,50.534 U_LDO.1 ; U_LDO.3 38.673,51.038 38.798,50.912 38.888,50.912 v1(38.9,50.9) 36.4,50.9 v1(35.95,50.45) 35.95,50.538 U_LDO.1 ; v1(45.788,35.138) 46.081,34.845 46.374,34.552 46.667,34.259 46.96,33.966 47.253,33.673 47.71,33.673 48.167,33.673 48.624,33.673 49.081,33.673 49.447,33.717 49.814,33.762 50.15,33.9 50.65,33.4 50.619,32.931 50.45,32.793 ; 52.025,31.22 52.491,31.217 52.995,31.217 C_VBUS.1 55.127,30.312 56.204,31.389 56.273,31.389 v1(56.388,31.504) ; v1(59.027,37.156) 68.488,46.617 R_BL1.1 ; R_BL1.1 68.488,56.487 69.65,57.65 70.9,57.65 72.15,56.4 72.4,56.4 72.4,56.387 R_BL2.1 72.792,55.995 73.097,55.691 ; v1(74.009,55.308) 74.835,55.308 v1(75,55.143) 75.33,55.143 R_BL3.1 76.488,56.487 77.65,57.65 79.137,57.65 R_BL4.1
  Bottom w0.5: v1(40.948,40.515) 40.948,39.978 v1(45.788,35.138) ; v1(56.388,31.504) 56.388,34.445 58.904,36.961 58.904,37.033 v1(59.027,37.156)
VCC_3V3: C_3V3_BULK.1 C_LDO_OUT.1 C_MCU_BULK.1 C_MCU_VDD.1 C_TFT_VCI.1 C_TFT_VDDI1.1 C_TFT_VDDI2.1 C_VUSB.1 J_DEBUG.1 J_DISPLAY.7 J_DISPLAY.8 J_DISPLAY.9 J_DISPLAY.35 J_DISPLAY.40 J_DISPLAY.41 J_DISPLAY.42 R_DISPLAY_CS.2 R_DISPLAY_RESET.2 R_MCU_RESET.2 U_LDO.5 U_MAIN.29 U_MAIN.40 | length 137.8
  Top w0.3: U_MAIN.29@50.65,46.8 50.65,46.923 50.65,47.237 U_MAIN.29 50.65,47.65 50.65,47.75 50.65,47.85 50.65,47.95 50.65,48.05 50.65,48.15 50.65,48.25 50.65,48.3 50.65,48.35 ; 52.566,42.167 52.924,42.15 53.299,42.15 ; U_MAIN.40@53.675,42.15 U_MAIN.40 54.15,42.15 54.25,42.15 54.35,42.15 54.45,42.15 54.55,42.15 54.65,42.15 54.75,42.15 U_MAIN.40@54.8,42.15 ; v1@83.544,46.65 83.829,46.65 84.115,46.65 J_DISPLAY.35 84.3,46.65 84.2,46.65 84.1,46.65 84,46.65 83.9,46.65 83.8,46.65 83.775,46.65 v1@83.7,46.65 ; J_DISPLAY.9@83.775,33.65 84.059,33.65 J_DISPLAY.9 J_DISPLAY.9@84.4,33.5 ; J_DISPLAY.40@83.775,49.204 84.346,49.204 J_DISPLAY.40 J_DISPLAY.40@84.4,49.3 ; J_DISPLAY.7 J_DISPLAY.7@84.4,32.8 ; J_DISPLAY.8@84.4,33 J_DISPLAY.8 84.4,33.3 ; J_DISPLAY.41@84.4,49.5 J_DISPLAY.41 J_DISPLAY.41@84.4,49.8 ; J_DISPLAY.42@84.4,50 J_DISPLAY.42
  Top w0.312: 53.299,42.15 U_MAIN.40@53.675,42.15
  Top w0.325: v1(50.371,46.31) 50.374,46.3 50.374,46.186 50.374,45.799 50.374,45.413 50.374,45.027 50.374,44.641 50.374,44.255 50.374,43.869 50.374,43.482 50.374,43.096 50.374,42.71 v1(50.374,42.324) ; 52.208,42.183 52.566,42.167
  Top w0.328: J_DISPLAY.7@83.775,32.736 84.4,32.75 J_DISPLAY.7@84.367,32.683
  Top w0.363: 51.917,42.217 52.208,42.183
  Top w0.375: 50.43,29.975 50.53,30.075 v1(50.578,30.07)
  Top w0.4: J_DEBUG.1 32.234,56.236 32.498,55.972 32.762,55.708 33.026,55.444 33.29,55.18 33.554,54.916 33.554,54.557 33.554,54.199 33.418,53.043 33.2,53.7 32.125,53.675 32,53.7 31.8,53.3 31.85,52.225 32.181,52.033 32.511,51.842 32.842,51.65 33.009,51.5 33.278,51.192 35.6,49.5 35.737,49.475 35.975,49.238 36.212,49 U_LDO.5 ; C_MCU_BULK.1 40.177,45.65 39.566,46.261 39.448,46.261 v1(39.423,46.237) 37.864,46.237 37.554,46.547 v1(37.537,46.564) 36.7,47.3 U_LDO.5 ; R_MCU_RESET.2 47.835,29.975 C_VUSB.1 49.743,29.975 50.086,29.975 50.43,29.975 ; v1(50.371,46.31) 50.511,46.46 50.65,46.61 50.65,46.8 ; v1(50.374,42.324) 50.461,42.237 50.586,42.237 50.673,42.15 51.048,42.15 51.423,42.15 51.625,42.25 51.917,42.217 ; v1(50.578,30.07) 50.972,30.07 51.367,30.07 51.761,30.07 52.155,30.07 52.55,30.07 52.944,30.07 53.339,30.07 53.733,30.07 54.127,30.07 54.522,30.07 54.916,30.07 55.31,30.07 55.705,30.07 56.099,30.07 56.493,30.07 56.888,30.07 57.282,30.07 57.534,30.322 57.785,30.573 58.037,30.825 58.289,31.077 58.54,31.329 v1(58.588,31.311) 59.4,30.7 59.387,30.505 59.653,30.237 59.92,29.969 R_DISPLAY_CS.2 ; 50.65,48.35 50.65,50.203 46.731,54.122 45.71,54.122 C_3V3_BULK.1 44.267,53.121 44.046,53.341 43.826,53.562 43.46,53.562 43.093,53.562 42.6,53.7 41.4,53.7 41.262,53.562 41.237,53.562 41.016,53.341 40.796,53.121 C_LDO_OUT.1 40.461,52.9 39.481,51.92 39.481,51.908 v1(39.406,51.842) 38.733,51.833 35.828,48.928 v1(35.8,48.9) 36.312,48.9 U_LDO.5 ; 54.8,42.15 54.85,42.15 C_MCU_VDD.1 56.513,41.839 56.479,38.066 59.91,34.645 R_DISPLAY_CS.2 ; v1(76.8,30.6) 76.764,30.564 76.764,30.542 76.575,30.353 C_TFT_VCI.1 76.575,30.296 76.154,30.696 76.08,30.697 v1(76.088,30.709) 75.048,30.76 75.023,30.735 75.02,30.735 v1(74.975,30.919) 74.72,30.73 C_TFT_VDDI2.1 73.61,30.18 73.33,30.46 72.954,30.46 71.6,30.7 71.17,30.18 C_TFT_VDDI1.1 70.89,30.19 70.388,30.692 v1(70.38,30.7) 68.706,30.7 67.946,31.459 67.934,31.459 v1(67.909,31.484) 64.487,31.477 R_DISPLAY_RESET.2 62.657,30.153 62.405,30.405 62.2,30.7 60.772,30.405 60.415,30.405 60.163,30.153 R_DISPLAY_CS.2 ; v1(77.305,32.683) 81.272,32.726 83.482,32.729 J_DISPLAY.7@83.775,32.736 ; v1(83.046,34.323) 83.27,34.099 83.5,33.7 83.719,33.65 J_DISPLAY.9@83.775,33.65 ; v1@83.544,46.65 83.499,46.605 83.509,46.605 v1(83.559,46.694) ; v1@83.7,46.65 83.651,46.65 83.65,46.651 83.602,46.651 83.601,46.652 v1(83.225,46.775) 83.579,49.059 83.498,49.14 83.498,49.199 v1(83.493,49.204) J_DISPLAY.40@83.775,49.204 ; J_DISPLAY.7@84.367,32.683 J_DISPLAY.7 ; 84.4,32.8 J_DISPLAY.8@84.4,33 ; 84.4,33.3 J_DISPLAY.9@84.4,33.5 ; 84.4,49.3 J_DISPLAY.41@84.4,49.5 ; 84.4,49.8 J_DISPLAY.42@84.4,50
  Bottom w0.4: v1(76.8,30.6) 76.8,32.178 77.273,32.651 v1(77.305,32.683) ; v1(83.046,34.323) 83.031,34.338 83.031,34.43 83.305,34.704 83.579,34.978 83.578,35.368 83.577,35.759 83.577,36.149 83.576,36.54 83.575,36.93 83.575,37.321 83.574,37.711 83.573,38.102 83.573,38.492 83.572,38.883 83.572,39.273 83.571,39.664 83.57,40.055 83.57,40.445 83.569,40.836 83.568,41.226 83.568,41.617 83.567,42.007 83.566,42.398 83.566,42.788 83.565,43.179 83.564,43.569 83.564,43.96 83.563,44.351 83.562,44.741 83.562,45.132 83.561,45.522 83.561,45.913 83.56,46.303 v1(83.559,46.694)
pads on no net: J_DISPLAY.11 J_DISPLAY.12 J_DISPLAY.13 J_DISPLAY.14 J_DISPLAY.44 J_DISPLAY.45 J_DISPLAY.46 J_DISPLAY.47 J_DISPLAY.51 J_DISPLAY.52 J_USB.5 J_USB.11 J_USB.NPTH-1 J_USB.NPTH-2 U_LDO.4 U_MAIN.1 U_MAIN.2 U_MAIN.3 U_MAIN.4 U_MAIN.5 U_MAIN.6 U_MAIN.7 U_MAIN.8 U_MAIN.9 U_MAIN.10 U_MAIN.11 U_MAIN.14 U_MAIN.15 U_MAIN.16 U_MAIN.17 U_MAIN.18 U_MAIN.19 U_MAIN.20 U_MAIN.21 U_MAIN.22 U_MAIN.23 U_MAIN.24 U_MAIN.25 U_MAIN.26 U_MAIN.27 U_MAIN.28 U_MAIN.33 U_MAIN.34 U_MAIN.35 U_MAIN.36 U_MAIN.37 U_MAIN.39 U_MAIN.43 U_MAIN.44 U_MAIN.45 U_MAIN.46 U_MAIN.47 U_MAIN.48 U_MAIN.49 U_MAIN.54 U_MAIN.55 U_MAIN.56 U_MAIN.57 U_MAIN.62 U_MAIN.63 U_MAIN.64

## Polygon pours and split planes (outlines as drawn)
GND on Bottom (solid): 26.886,58.1 25.7,58.1 25.7,46.796 25.725,46.826 25.854,46.932 26.001,47.01 26.16,47.059 26.326,47.075 26.476,47.075 26.476,46.825 26.326,46.825 26.209,46.814 26.096,46.779 25.993,46.724 25.902,46.649 25.827,46.558 25.772,46.455 25.747,46.375 25.7,46.375 25.7,46.075 25.747,46.075 25.772,45.996 25.827,45.892 25.902,45.801 25.993,45.726 26.096,45.671 26.209,45.637 26.326,45.625 26.476,45.625 26.476,45.375 26.326,45.375 26.16,45.391 26.001,45.44 25.854,45.518 25.725,45.624 25.7,45.654 25.7,38.146 25.725,38.176 25.854,38.282 26.001,38.36 26.16,38.409 26.326,38.425 26.476,38.425 26.476,38.175 26.326,38.175 26.209,38.163 26.096,38.129 25.993,38.074 25.902,37.999 25.827,37.908 25.772,37.804 25.747,37.725 25.7,37.725 25.7,37.425 25.747,37.425 25.772,37.345 25.827,37.242 25.902,37.151 25.993,37.076 26.096,37.021 26.209,36.986 26.326,36.975 26.476,36.975 26.476,36.725 26.326,36.725 26.16,36.741 26.001,36.79 25.854,36.868 25.725,36.974 25.7,37.004 25.7,25.7 26.886,25.7 26.864,25.707 26.622,25.836 26.41,26.01 26.236,26.222 26.107,26.464 26.027,26.727 26,27 26.027,27.273 26.107,27.536 26.236,27.778 26.41,27.99 26.622,28.164 26.864,28.293 27.127,28.373 27.4,28.4 27.673,28.373 27.936,28.293 28.178,28.164 28.39,27.99 28.564,27.778 28.693,27.536 28.773,27.273 28.8,27 28.773,26.727 28.693,26.464 28.564,26.222 28.39,26.01 28.178,25.836 27.936,25.707 27.914,25.7 89.1,25.7 89.1,58.1 27.914,58.1 27.936,58.093 28.178,57.964 28.39,57.79 28.564,57.578 28.693,57.336 28.773,57.073 28.8,56.8 28.773,56.527 28.693,56.264 28.564,56.022 28.39,55.81 28.178,55.636 27.936,55.507 27.673,55.427 27.4,55.4 27.127,55.427 26.864,55.507 26.622,55.636 26.41,55.81 26.236,56.022 26.107,56.264 26.027,56.527 26,56.8 26.027,57.073 26.107,57.336 26.236,57.578 26.41,57.79 26.622,57.964 26.864,58.093

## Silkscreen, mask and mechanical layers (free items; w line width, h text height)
Top Overlay:
  text "4L • BOTTOM GND POUR" at 39.4,56.9 h0.48
  text "ER-CON50HT-1 • 4-WIRE SPI" at 67.4,56.9 h0.55
  text "ER-TFT028A2-4" at 64.4,27.05 h0.58
  text "QUICK CONFIGURE • SCREEN" at 57.4,26.9 h0.72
